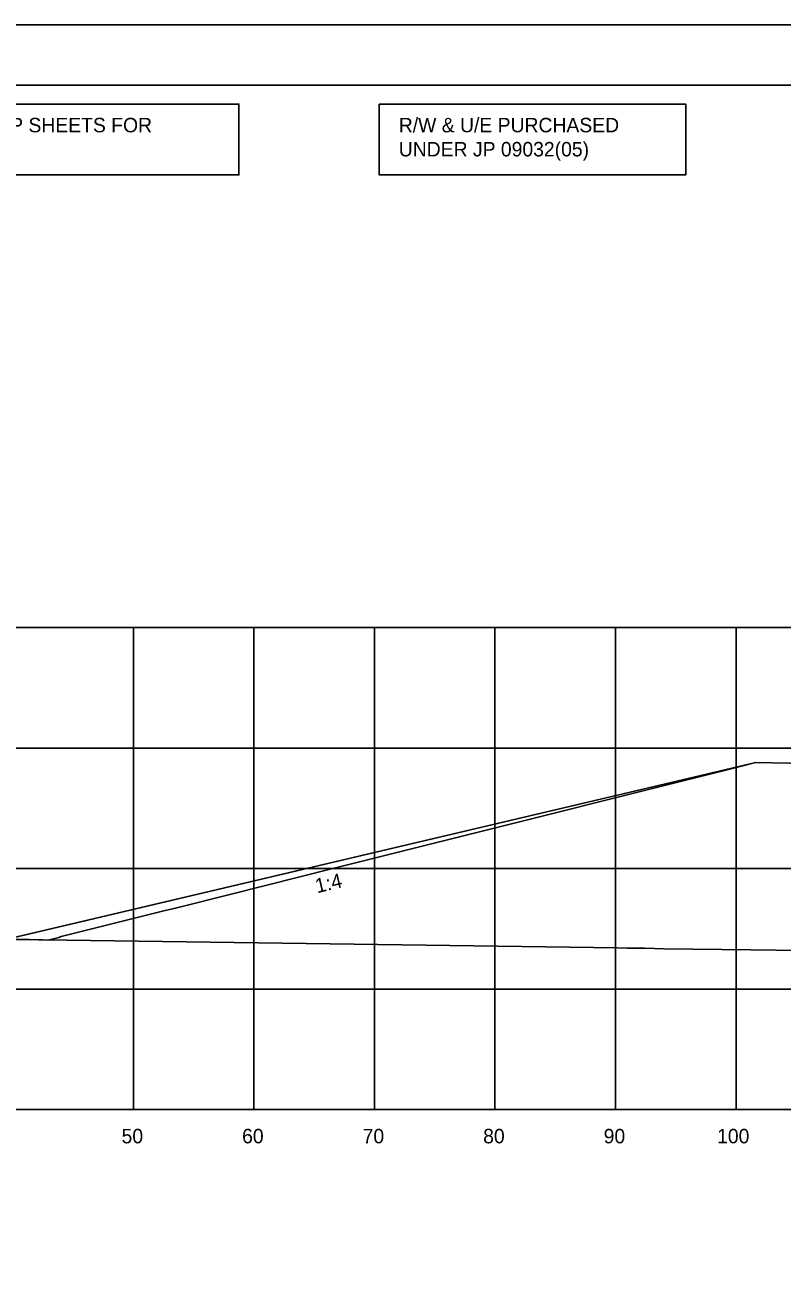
# Model space of a CAD drawing. Extents: x 2148105 to 2149976, y 144169 to 149705.
# Drawn here: x 2148454.3 to 2148517.1, y 149353.3 to 149456.9 of the extents above; entities that cross this region are included whole.
import ezdxf

# ---------------------------------------------------------------- set-up
doc = ezdxf.new("R2010")
doc.units = 0
for name, color, linetype in [('INR_Tracking', 7, 'Continuous'), ('PH1a-PR-DividingStrip', 7, 'Continuous'), ('PH1a-PR-ServRd', 7, 'Continuous'), ('PR-ApproachSlab', 7, 'Continuous'), ('PR-SHLDR-RMP-H', 7, 'Continuous'), ('PR_Align_Ramp_J', 7, 'Continuous'), ('PR_Storm_Conc_Box_PH1B', 7, 'Continuous'), ('PR_Storm_Conc_Pipe_PH1B', 7, 'Continuous'), ('PR_Storm_Inlet_CICI_PH1B', 7, 'Continuous'), ('PR_Storm_MH', 7, 'Continuous'), ('PR_Storm_MH_PH1B', 7, 'Continuous'), ('PR_Storm_Standard_Median_Drain_PH1B', 7, 'Continuous'), ('TopCut', 7, 'Continuous')]:
    doc.layers.add(name, color=color, linetype=linetype)

msp = doc.modelspace()

# ---------------------------------------------------------------- linework, layer by layer
at = {"layer": 'INR_Tracking'}
msp.add_lwpolyline([(2148400.41, 149382.2), (2148412.19, 149381.6), (2148413.32, 149381.54), (2148413.58, 149381.53), (2148415.32, 149381.44), (2148415.43, 149381.44), (2148423.32, 149381.03), (2148423.32, 149381.03), (2148423.58, 149381.02), (2148425.31, 149380.93), (2148425.31, 149380.93), (2148429.19, 149380.73), (2148429.19, 149380.73), (2148429.19, 149380.73), (2148429.43, 149380.67), (2148436.11, 149379), (2148443.21, 149379), (2148444.11, 149379), (2148444.11, 149379), (2148444.36, 149379.06), (2148510.4, 149394.63), (2148514.97, 149395.71)], dxfattribs=at)
at = {"layer": 'PH1a-PR-ServRd'}
msp.add_lwpolyline([(2148570.82, 149241.91), (2148255.82, 149241.91), (2148255.82, 149451.91), (2148570.82, 149451.91)], close=True, dxfattribs=at)
at = {"layer": 'PR-ApproachSlab'}
msp.add_lwpolyline([(2148456.25, 149380.98), (2148457.13, 149381.2), (2148457.33, 149381.26), (2148464.75, 149383.12), (2148465.95, 149383.42), (2148466.92, 149383.66), (2148471.44, 149384.79), (2148479.88, 149386.91), (2148485.29, 149388.27), (2148493.93, 149390.43), (2148498.89, 149391.68), (2148501.96, 149392.45), (2148512.25, 149395.03), (2148514.97, 149395.71), (2148516.29, 149395.68), (2148519.27, 149395.63)], dxfattribs=at)
at = {"layer": 'PR-SHLDR-RMP-H'}
msp.add_lwpolyline([(2148456.25, 149380.98), (2148457.13, 149381.2), (2148457.33, 149381.26), (2148464.75, 149383.12), (2148465.95, 149383.42), (2148466.92, 149383.66), (2148471.44, 149384.79), (2148479.88, 149386.91), (2148485.29, 149388.27), (2148493.93, 149390.43), (2148498.89, 149391.68), (2148501.96, 149392.45), (2148512.25, 149395.03), (2148514.97, 149395.71), (2148516.29, 149395.68), (2148519.27, 149395.63)], dxfattribs=at)
at = {"layer": 'PR_Align_Ramp_J'}
msp.add_lwpolyline([(2148236.32, 149456.91), (2148576.32, 149456.91), (2148576.32, 149236.91), (2148236.32, 149236.91)], close=True, dxfattribs=at)
at = {"layer": 'PR_Storm_Conc_Box_PH1B'}
for p, q in [((2148263.32, 149406.91), (2148563.32, 149406.91)), ((2148463.32, 149366.91), (2148463.32, 149406.91)), ((2148473.32, 149366.91), (2148473.32, 149406.91)), ((2148483.32, 149366.91), (2148483.32, 149406.91)), ((2148493.32, 149366.91), (2148493.32, 149406.91)), ((2148503.32, 149366.91), (2148503.32, 149406.91)), ((2148513.32, 149366.91), (2148513.32, 149406.91)), ((2148263.32, 149396.91), (2148563.32, 149396.91)), ((2148263.32, 149386.91), (2148563.32, 149386.91)), ((2148263.32, 149376.91), (2148563.32, 149376.91)), ((2148263.32, 149366.91), (2148563.32, 149366.91))]:
    msp.add_line(p, q, dxfattribs=at)
at = {"layer": 'PR_Storm_Conc_Pipe_PH1B'}
msp.add_lwpolyline([(2148255.82, 149241.91), (2148570.82, 149241.91), (2148570.82, 149451.91), (2148255.82, 149451.91)], close=True, dxfattribs=at)
msp.add_lwpolyline([(2148255.82, 149241.91), (2148570.82, 149241.91), (2148570.82, 149451.91), (2148255.82, 149451.91)], close=True, dxfattribs=at)
at = {"layer": 'PR_Storm_Inlet_CICI_PH1B'}
msp.add_lwpolyline([(2148447.8, 149381.1), (2148503.48, 149380.33), (2148504.29, 149380.31), (2148505.76, 149380.29), (2148507.34, 149380.26), (2148514.56, 149380.17), (2148552.28, 149379.66), (2148557.23, 149379.61), (2148563.32, 149379.55)], dxfattribs=at)
at = {"layer": 'PR_Storm_MH'}
for points in [[(2148431.78, 149450.34), (2148472.07, 149450.34), (2148472.07, 149444.47), (2148431.78, 149444.47)], [(2148483.72, 149450.34), (2148509.15, 149450.34), (2148509.15, 149444.47), (2148483.72, 149444.47)]]:
    msp.add_lwpolyline(points, close=True, dxfattribs=at)
at = {"layer": 'PR_Storm_Standard_Median_Drain_PH1B'}
msp.add_line((2148263.32, 149366.91), (2148563.32, 149366.91), dxfattribs=at)
at = {"layer": 'TopCut'}
msp.add_lwpolyline([(2148452.73, 149381.03), (2148453.34, 149381.02), (2148454.63, 149381.01), (2148456.25, 149380.98), (2148457.13, 149381.2), (2148457.33, 149381.26), (2148464.75, 149383.12), (2148465.95, 149383.42), (2148466.92, 149383.66), (2148471.44, 149384.79), (2148479.88, 149386.91), (2148485.29, 149388.27), (2148493.93, 149390.43), (2148498.89, 149391.68), (2148501.96, 149392.45), (2148512.25, 149395.03), (2148514.96, 149395.71), (2148510.4, 149394.63)], close=True, dxfattribs=at)

# ---------------------------------------------------------------- texts
at = {"layer": 'PH1a-PR-DividingStrip'}
msp.add_text('1:4', height=1.2, rotation=13.2664, dxfattribs=at).set_placement((2148478.56, 149384.86))
at = {"layer": 'PR_Storm_MH'}
for s, p in [('R/W & U/E PURCHASED', (2148485.34, 149448)), ('SEE DRAINAGE AREA MAP SHEETS FOR', (2148433.39, 149448)), ('UNDER JP 09032(05)', (2148485.34, 149446))]:
    msp.add_text(s, height=1.2, dxfattribs=at).set_placement(p)
at = {"layer": 'PR_Storm_MH_PH1B'}
for s, p in [('50', (2148462.34, 149364.11)), ('60', (2148472.34, 149364.11)), ('70', (2148482.34, 149364.11)), ('80', (2148492.34, 149364.11)), ('90', (2148502.34, 149364.11)), ('100', (2148511.75, 149364.11))]:
    msp.add_text(s, height=1.2, dxfattribs=at).set_placement(p)

doc.saveas('drawing.dxf')
